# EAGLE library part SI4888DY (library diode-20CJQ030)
Vishay Siliconix Si4888DY N-Channel Reduced Qg, Fast Switching MOSFET FEATURES: TrenchFET Power MOSFET PWM Optimized High-Efficiency 100% Rg Tested Please send any comments to: messi@users.sourceforge.net
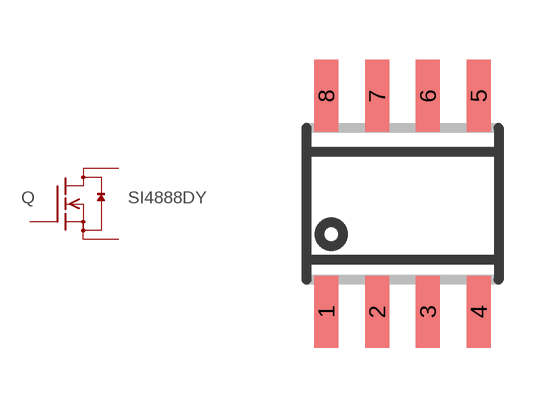
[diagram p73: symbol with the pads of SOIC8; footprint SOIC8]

Designator prefix Q

## SI4888DY  [SOIC8]
1  S  pas
2  S  pas
3  S  pas
4  G  pas
5  D  pas
6  D  pas
7  D  pas
8  D  pas

## Footprint SOIC8 (pad centres in mm)
Small Outline IC
smd 0.6 x 1.8: 1 -1.905,-2.7; 2 -0.635,-2.7; 3 0.635,-2.7; 4 1.905,-2.7; 5 1.905,2.7; 6 0.635,2.7; 7 -0.635,2.7; 8 -1.905,2.7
